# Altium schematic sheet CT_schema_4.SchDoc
size 283 x 173 mm
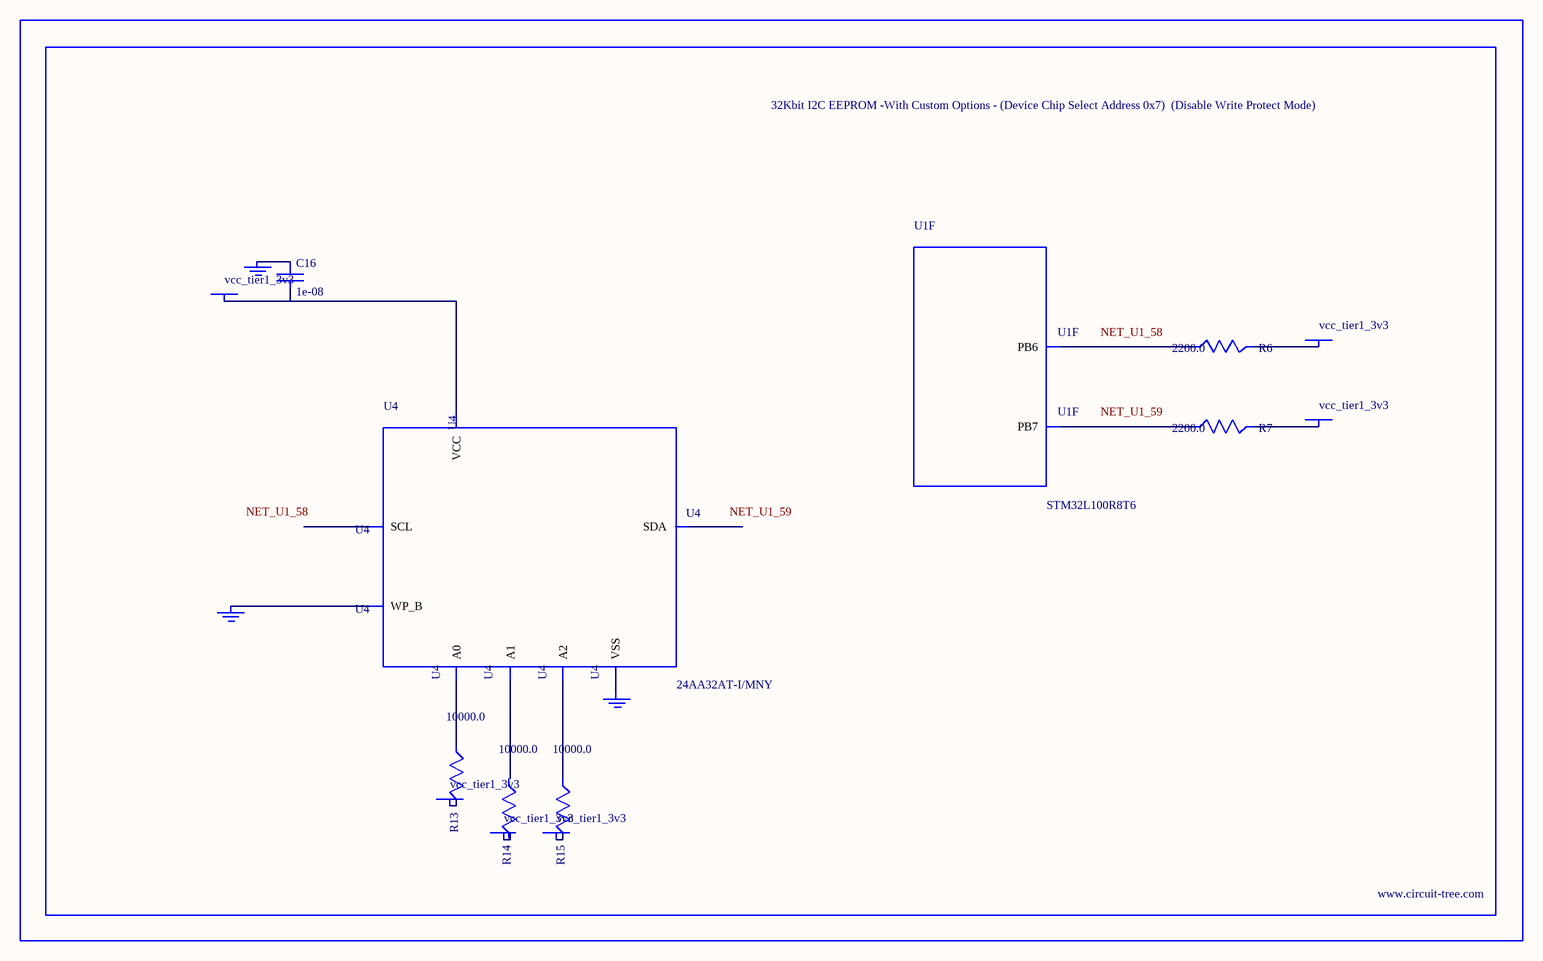
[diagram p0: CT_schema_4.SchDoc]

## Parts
BORDER3  (no value)
C16  1e-08  [C0402]
GND_INSTANCE_3_0  (no value)
GND_INSTANCE_3_1  (no value)
GND_INSTANCE_3_2  (no value)
POWER_INSTANCE_3_0  vcc_tier1_3v3
POWER_INSTANCE_3_1  vcc_tier1_3v3
POWER_INSTANCE_3_2  vcc_tier1_3v3
POWER_INSTANCE_3_3  vcc_tier1_3v3
POWER_INSTANCE_3_4  vcc_tier1_3v3
POWER_INSTANCE_3_5  vcc_tier1_3v3
R6  2200.0  [R0603]
R7  2200.0  [R0603]
R13  10000.0  [R0603]
R14  10000.0  [R0603]
R15  10000.0  [R0603]
U1  STM32L100R8T6  [LQFP64]  (part F of 7)
U4  24AA32AT-I/MNY  [TDFN-8/6MM]

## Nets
NetC16_1: C16.1 GND_INSTANCE_3_1.0(GND)
NetC16_2: C16.2 POWER_INSTANCE_3_3.0(PWR) U4.8(VCC)
NetGND_INSTANCE_3_0_0: GND_INSTANCE_3_0.0(GND) U4.7(WP_B)
NetGND_INSTANCE_3_2_0: GND_INSTANCE_3_2.0(GND) U4.4(VSS)
NetPOWER_INSTANCE_3_0_0: POWER_INSTANCE_3_0.0(PWR) R13.2
NetPOWER_INSTANCE_3_2_0: POWER_INSTANCE_3_2.0(PWR) R15.2
NetPOWER_INSTANCE_3_4_0: POWER_INSTANCE_3_4.0(PWR) R6.2
NetPOWER_INSTANCE_3_5_0: POWER_INSTANCE_3_5.0(PWR) R7.2
NetR6_1: R6.1 U1.58(PB6)
NetR7_1: R7.1 U1.59(PB7)
NetR13_1: R13.1 U4.1(A0)
NetR15_1: R15.1 U4.3(A2)

Not connected (* = marked no-connect by the designer): POWER_INSTANCE_3_1 0(PWR); R14 1 2; U4 2(A1) 5(SDA) 6(SCL)

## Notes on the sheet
- Labels drawn without touching a wire or pin: NET_U1_58, NET_U1_59

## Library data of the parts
BORDER3 = BORDER_PAGE3
C16 = C0402C103K3RAC
GND_INSTANCE_3_0-GND_INSTANCE_3_2 = GND
POWER_INSTANCE_3_0-POWER_INSTANCE_3_5 = PWR
R6 R7 = RC0603JR-072K2L
R13-R15 = RC0603JR-0710KL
